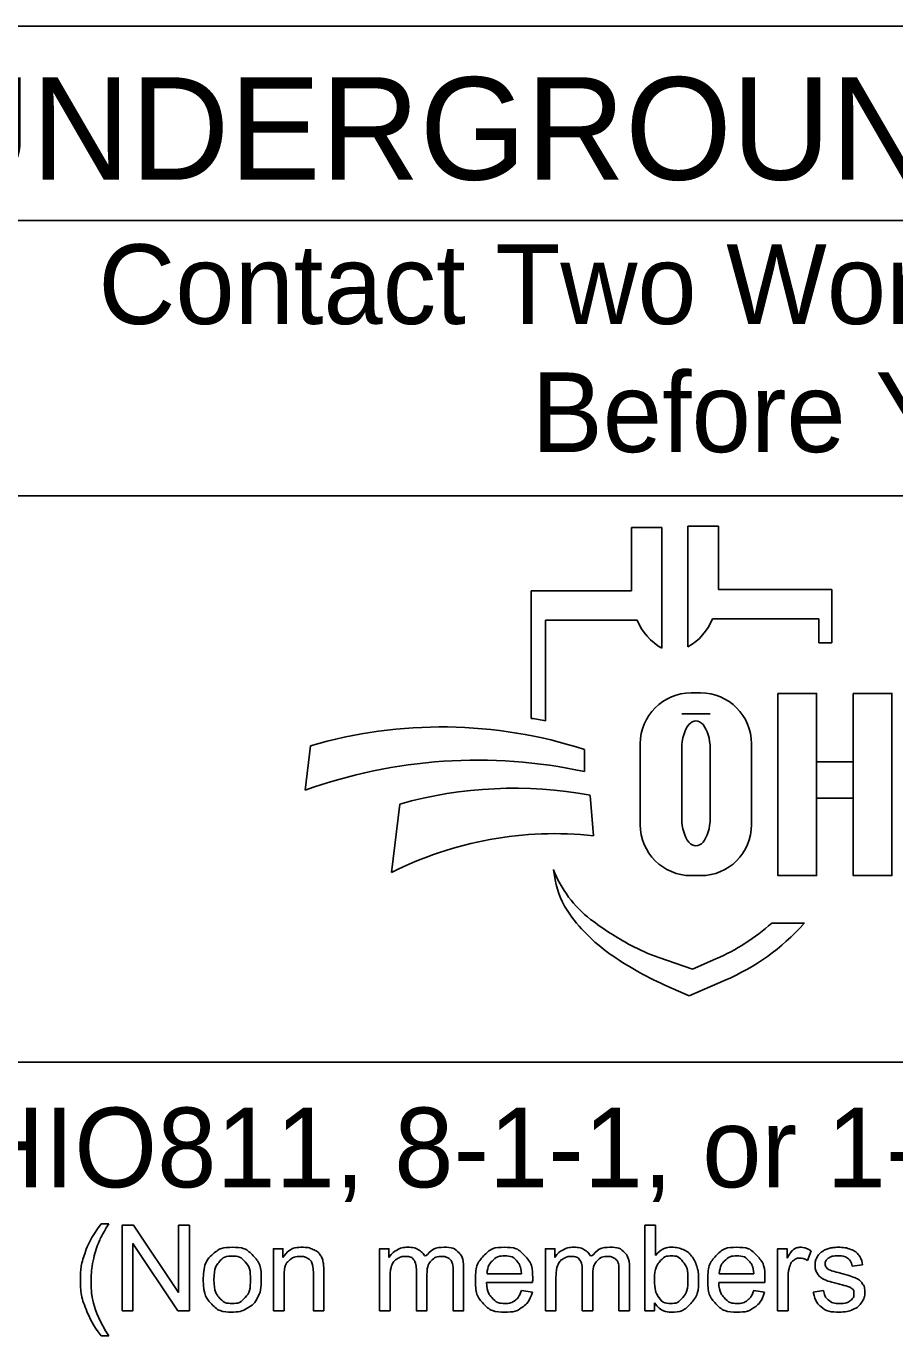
# Model space of a CAD drawing. Extents: x 0 to 34, y 0 to 22.
# Drawn here: x 2.67 to 4.196, y 2.18 to 4.48 of the extents above; entities that cross this region are included whole.
import ezdxf

# ---------------------------------------------------------------- set-up
doc = ezdxf.new("R2010")
doc.units = 0
doc.layers.add('SH_Data', color=7, linetype='Continuous')
doc.layers.add('SH_Text', color=7, linetype='Continuous')

msp = doc.modelspace()

# ---------------------------------------------------------------- linework, layer by layer
at = {"layer": 'SH_Data'}
for p, q in [((6.6275, 4.4803), (2.3775, 4.4803)), ((2.3775, 4.1387), (6.6275, 4.1387)), ((2.3775, 3.6553), (6.6275, 3.6553)), ((6.6275, 2.6607), (2.3775, 2.6607))]:
    msp.add_line(p, q, dxfattribs=at)
at = {"layer": 'SH_Text'}
for p, q in [((3.7335, 3.4883), (3.7335, 3.5998)), ((3.7335, 3.5998), (3.7872, 3.5998)), ((3.7872, 3.5998), (3.7872, 3.3877)), ((3.8329, 3.39), (3.8329, 3.6021)), ((3.8329, 3.6021), (3.8865, 3.6021)), ((3.8865, 3.6021), (3.8865, 3.4906)), ((3.5576, 3.2644), (3.5576, 3.4883)), ((3.5576, 3.4883), (3.7335, 3.4883)), ((3.8865, 3.4906), (4.0857, 3.4906)), ((4.0857, 3.4906), (4.0857, 3.3968)), ((3.5828, 3.4369), (3.5828, 3.26)), ((3.7439, 3.4369), (3.5828, 3.4369)), ((4.0625, 3.4392), (3.8761, 3.4392)), ((4.0625, 3.3968), (4.0625, 3.4392)), ((4.0857, 3.3968), (4.0625, 3.3968)), ((3.8385, 3.3091), (3.8551, 3.3091)), ((3.8718, 3.2721), (3.822, 3.2721)), ((3.1602, 3.1381), (3.1696, 3.2162)), ((3.6509, 3.2097), (3.6509, 3.1709)), ((3.7491, 3.0776), (3.7491, 3.2196)), ((3.822, 3.089), (3.822, 3.2114)), ((3.8718, 3.2114), (3.8718, 3.089)), ((3.9445, 3.2196), (3.9445, 3.0776)), ((3.6608, 3.1291), (3.6671, 3.0582)), ((3.312, 2.9936), (3.3267, 3.1137)), ((3.5997, 2.9807), (3.5967, 2.9986)), ((3.8551, 2.9882), (3.8385, 2.9882)), ((3.98, 2.9048), (4.0375, 2.9048)), ((3.7816, 2.8444), (3.841, 2.8239)), ((3.841, 2.8239), (3.8821, 2.8417)), ((3.835, 2.7769), (3.7976, 2.7934)), ((3.8983, 2.8044), (3.835, 2.7769))]:
    msp.add_line(p, q, dxfattribs=at)
for points in [[(3.991, 3.3081), (4.0589, 3.3081), (4.0589, 2.9881), (3.991, 2.9881)], [(4.1231, 3.3081), (4.1911, 3.3081), (4.1911, 2.9881), (4.1231, 2.9881)], [(4.0589, 3.1882), (4.1231, 3.1882), (4.1231, 3.1242), (4.0589, 3.1242)]]:
    msp.add_lwpolyline(points, close=True, dxfattribs=at)
for points in [[(2.8021, 2.3766), (2.8153, 2.3766)], [(2.8389, 2.2239), (2.8389, 2.3741), (2.8592, 2.3741), (2.9382, 2.2561), (2.9382, 2.3741), (2.9572, 2.3741), (2.9572, 2.2239), (2.9369, 2.2239), (2.8579, 2.3419), (2.8579, 2.2239), (2.8389, 2.2239)], [(3.7743, 2.2239), (3.7573, 2.2239), (3.7573, 2.3741), (3.7757, 2.3741), (3.7757, 2.3206)], [(3.1048, 2.2239), (3.1048, 2.3328), (3.1214, 2.3328), (3.1214, 2.3173)], [(3.2912, 2.2239), (3.2912, 2.3328), (3.3077, 2.3328), (3.3077, 2.3174)], [(3.5826, 2.2239), (3.5826, 2.3328), (3.5991, 2.3328), (3.5991, 2.3174)], [(3.9904, 2.2239), (3.9904, 2.3328), (4.007, 2.3328), (4.007, 2.3163)], [(4.0495, 2.3293), (4.043, 2.3122)], [(4.1394, 2.3046), (4.1213, 2.3022)], [(3.1233, 2.2833), (3.1233, 2.2239), (3.1048, 2.2239)], [(3.1932, 2.2908), (3.1932, 2.2239), (3.1748, 2.2239), (3.1748, 2.2901)], [(3.3097, 2.2803), (3.3097, 2.2239), (3.2912, 2.2239)], [(3.3743, 2.2871), (3.3743, 2.2239), (3.3559, 2.2239), (3.3559, 2.2946)], [(3.4388, 2.2986), (3.4388, 2.2239), (3.4203, 2.2239), (3.4203, 2.2924)], [(3.4799, 2.2887), (3.5406, 2.2887)], [(3.601, 2.2803), (3.601, 2.2239), (3.5826, 2.2239)], [(3.6657, 2.2871), (3.6657, 2.2239), (3.6473, 2.2239), (3.6473, 2.2946)], [(3.7301, 2.2986), (3.7301, 2.2239), (3.7117, 2.2239), (3.7117, 2.2924)], [(3.8879, 2.2887), (3.9486, 2.2887)], [(4.0088, 2.2809), (4.0088, 2.2239), (3.9904, 2.2239)], [(3.56, 2.2736), (3.4788, 2.2736)], [(3.5404, 2.2591), (3.5595, 2.2567)], [(3.968, 2.2736), (3.8868, 2.2736)], [(3.9484, 2.2591), (3.9675, 2.2567)], [(4.053, 2.2564), (4.0712, 2.2593)], [(3.7743, 2.2375), (3.7743, 2.2239)], [(2.8153, 2.1798), (2.8021, 2.1798)]]:
    msp.add_lwpolyline(points, dxfattribs=at)
for centre, radius, start, end in [((3.8353, 3.4736), 0.0985, 201.9296, 240.7469), ((3.7847, 3.476), 0.0985, 299.2531, 338.0704), ((3.8385, 3.2196), 0.0895, 90, 180), ((3.8551, 3.2196), 0.0895, 0, 90), ((3.3997, 2.4302), 0.8191, 72.1402, 106.3144), ((3.4295, 2.4554), 0.8191, 79.2074, 81.0007), ((3.4628, 2.2991), 0.8919, 77.8238, 109.8274), ((3.5267, 2.4094), 0.7322, 79.44, 105.8467), ((3.5987, 2.4262), 0.6357, 83.8248, 116.8021), ((3.8385, 3.0776), 0.0895, 180, 270), ((3.8551, 3.0776), 0.0895, 270, 0), ((3.7841, 3.0707), 0.2008, 201.0457, 232.5314), ((3.741, 3.0048), 0.1433, 189.6817, 216.0884), ((3.8747, 3.1022), 0.3088, 216.0884, 235.7167), ((3.9766, 3.3219), 0.5173, 232.5314, 241.794), ((3.7387, 3.1722), 0.3602, 293.4582, 312.0712), ((3.7387, 3.1722), 0.401, 293.4582, 317.8286), ((3.8914, 3.1631), 0.3371, 241.794, 250.9821), ((4.0412, 3.3465), 0.6044, 235.7167, 246.2325)]:
    msp.add_arc(centre, radius, start, end, dxfattribs=at)
for centre, start_param, end_param in [((3.8469, 3.2114), 4.712389, 7.853982), ((3.8469, 3.089), 1.570796, 4.712389)]:
    msp.add_ellipse(centre, major_axis=(0, 0.0484), ratio=0.514403, start_param=start_param, end_param=end_param, dxfattribs=at)
for points in [[(2.8021, 2.1798), (2.7869, 2.199), (2.7763, 2.2248), (2.7657, 2.2506), (2.7657, 2.2783), (2.7657, 2.3026), (2.7736, 2.325), (2.7829, 2.3509), (2.8021, 2.3766)], [(2.8153, 2.3766), (2.8029, 2.3553), (2.7989, 2.3462), (2.7927, 2.332), (2.7891, 2.3167), (2.7847, 2.2975), (2.7847, 2.2782), (2.7847, 2.2289), (2.8153, 2.1798)], [(2.9814, 2.2783), (2.9814, 2.3085), (2.9981, 2.3231), (3.0122, 2.3352), (3.0323, 2.3352), (3.0547, 2.3352), (3.069, 2.3205), (3.0832, 2.3058), (3.0832, 2.2799), (3.0832, 2.2589), (3.0769, 2.2469), (3.0706, 2.2348), (3.0586, 2.2282), (3.0466, 2.2215), (3.0323, 2.2215), (3.0095, 2.2215), (2.9954, 2.2362), (2.9814, 2.2508), (2.9814, 2.2783)], [(3.1214, 2.3173), (3.1334, 2.3352), (3.156, 2.3352), (3.1659, 2.3352), (3.1741, 2.3316), (3.1823, 2.3281), (3.1864, 2.3224), (3.1905, 2.3166), (3.1922, 2.3087), (3.1932, 2.3036), (3.1932, 2.2908)], [(3.3077, 2.3174), (3.3128, 2.3254), (3.3214, 2.3303), (3.3299, 2.3352), (3.3407, 2.3352), (3.3528, 2.3352), (3.3606, 2.3301), (3.3683, 2.3251), (3.3715, 2.3161), (3.3844, 2.3352), (3.4051, 2.3352), (3.4213, 2.3352), (3.43, 2.3262), (3.4388, 2.3172), (3.4388, 2.2986)], [(3.5595, 2.2567), (3.555, 2.24), (3.5428, 2.2307), (3.5306, 2.2215), (3.5117, 2.2215), (3.4878, 2.2215), (3.4738, 2.2362), (3.4598, 2.2509), (3.4598, 2.2774), (3.4598, 2.3049), (3.474, 2.32), (3.4881, 2.3352), (3.5106, 2.3352), (3.5324, 2.3352), (3.5463, 2.3203), (3.5601, 2.3055), (3.5601, 2.2785), (3.5601, 2.2769), (3.56, 2.2736)], [(3.5991, 2.3174), (3.6042, 2.3254), (3.6127, 2.3303), (3.6212, 2.3352), (3.6321, 2.3352), (3.6442, 2.3352), (3.6519, 2.3301), (3.6597, 2.3251), (3.6628, 2.3161), (3.6758, 2.3352), (3.6965, 2.3352), (3.7127, 2.3352), (3.7214, 2.3262), (3.7301, 2.3172), (3.7301, 2.2986)], [(3.7757, 2.3206), (3.7874, 2.3352), (3.8055, 2.3352), (3.8155, 2.3352), (3.8245, 2.3311), (3.8335, 2.3271), (3.8392, 2.3198), (3.845, 2.3124), (3.8483, 2.3021), (3.8516, 2.2918), (3.8516, 2.28), (3.8516, 2.252), (3.8378, 2.2368), (3.8239, 2.2215), (3.8046, 2.2215), (3.7853, 2.2215), (3.7743, 2.2375)], [(3.9675, 2.2567), (3.963, 2.24), (3.9508, 2.2307), (3.9386, 2.2215), (3.9196, 2.2215), (3.8958, 2.2215), (3.8818, 2.2362), (3.8678, 2.2509), (3.8678, 2.2774), (3.8678, 2.3049), (3.882, 2.32), (3.8961, 2.3352), (3.9186, 2.3352), (3.9404, 2.3352), (3.9543, 2.3203), (3.9681, 2.3055), (3.9681, 2.2785), (3.9681, 2.2769), (3.968, 2.2736)], [(4.007, 2.3163), (4.0133, 2.3278), (4.0187, 2.3315), (4.0241, 2.3352), (4.0305, 2.3352), (4.0398, 2.3352), (4.0495, 2.3293)], [(4.0712, 2.2593), (4.0727, 2.2483), (4.0798, 2.2425), (4.0868, 2.2366), (4.0995, 2.2366), (4.1122, 2.2366), (4.1184, 2.2418), (4.1245, 2.247), (4.1245, 2.254), (4.1245, 2.2602), (4.1191, 2.2638), (4.1153, 2.2663), (4.1002, 2.2701), (4.0799, 2.2752), (4.072, 2.2789), (4.0642, 2.2827), (4.0601, 2.2893), (4.0561, 2.2959), (4.0561, 2.3038), (4.0561, 2.3111), (4.0594, 2.3173), (4.0628, 2.3235), (4.0685, 2.3276), (4.0728, 2.3308), (4.0803, 2.333), (4.0877, 2.3352), (4.0962, 2.3352), (4.109, 2.3352), (4.1187, 2.3315), (4.1284, 2.3278), (4.133, 2.3215), (4.1377, 2.3152), (4.1394, 2.3046)], [(3.0003, 2.2783), (3.0003, 2.2574), (3.0094, 2.247), (3.0185, 2.2366), (3.0323, 2.2366), (3.046, 2.2366), (3.0551, 2.2471), (3.0642, 2.2575), (3.0642, 2.279), (3.0642, 2.2991), (3.0551, 2.3095), (3.0459, 2.3199), (3.0323, 2.3199), (3.0185, 2.3199), (3.0094, 2.3096), (3.0003, 2.2992), (3.0003, 2.2783)], [(3.1748, 2.2901), (3.1748, 2.3013), (3.1726, 2.3069), (3.1705, 2.3125), (3.165, 2.3158), (3.1595, 2.3191), (3.1521, 2.3191), (3.1404, 2.3191), (3.1318, 2.3117), (3.1233, 2.3042), (3.1233, 2.2833)], [(3.3559, 2.2946), (3.3559, 2.3069), (3.3514, 2.313), (3.3469, 2.3191), (3.3366, 2.3191), (3.3288, 2.3191), (3.3222, 2.315), (3.3156, 2.311), (3.3126, 2.3031), (3.3097, 2.2952), (3.3097, 2.2803)], [(3.4203, 2.2924), (3.4203, 2.3035), (3.4185, 2.3083), (3.4168, 2.3132), (3.412, 2.3162), (3.4073, 2.3191), (3.401, 2.3191), (3.3895, 2.3191), (3.3819, 2.3115), (3.3743, 2.3039), (3.3743, 2.2871)], [(3.5406, 2.2887), (3.5394, 2.3025), (3.5337, 2.3094), (3.5249, 2.3201), (3.5108, 2.3201), (3.4981, 2.3201), (3.4894, 2.3115), (3.4808, 2.303), (3.4799, 2.2887)], [(3.6473, 2.2946), (3.6473, 2.3069), (3.6428, 2.313), (3.6383, 2.3191), (3.628, 2.3191), (3.6202, 2.3191), (3.6136, 2.315), (3.607, 2.311), (3.604, 2.3031), (3.601, 2.2952), (3.601, 2.2803)], [(3.7117, 2.2924), (3.7117, 2.3035), (3.7099, 2.3083), (3.7081, 2.3132), (3.7034, 2.3162), (3.6987, 2.3191), (3.6923, 2.3191), (3.6809, 2.3191), (3.6733, 2.3115), (3.6657, 2.3039), (3.6657, 2.2871)], [(3.7741, 2.2792), (3.7741, 2.2596), (3.7794, 2.2509), (3.7881, 2.2366), (3.8029, 2.2366), (3.815, 2.2366), (3.8238, 2.2471), (3.8326, 2.2576), (3.8326, 2.2784), (3.8326, 2.2998), (3.8241, 2.3099), (3.8157, 2.3201), (3.8038, 2.3201), (3.7917, 2.3201), (3.7829, 2.3096), (3.7741, 2.299), (3.7741, 2.2792)], [(3.9486, 2.2887), (3.9474, 2.3025), (3.9417, 2.3094), (3.9328, 2.3201), (3.9188, 2.3201), (3.9061, 2.3201), (3.8974, 2.3115), (3.8888, 2.303), (3.8879, 2.2887)], [(4.043, 2.3122), (4.0363, 2.3162), (4.0295, 2.3162), (4.0235, 2.3162), (4.0187, 2.3125), (4.0139, 2.3089), (4.0119, 2.3024), (4.0088, 2.2926), (4.0088, 2.2809)], [(4.1213, 2.3022), (4.1201, 2.3106), (4.1142, 2.3153), (4.1083, 2.3201), (4.0975, 2.3201), (4.0848, 2.3201), (4.0794, 2.3159), (4.0739, 2.3116), (4.0739, 2.306), (4.0739, 2.3024), (4.0762, 2.2995), (4.0785, 2.2966), (4.0833, 2.2946), (4.086, 2.2936), (4.0996, 2.2899), (4.1192, 2.2847), (4.1269, 2.2813), (4.1347, 2.278), (4.1391, 2.2717), (4.1435, 2.2653), (4.1435, 2.2559), (4.1435, 2.2467), (4.1381, 2.2386), (4.1327, 2.2304), (4.1226, 2.226), (4.1124, 2.2215), (4.0996, 2.2215), (4.0784, 2.2215), (4.0672, 2.2303), (4.0561, 2.2391), (4.053, 2.2564)], [(3.4788, 2.2736), (3.4799, 2.2557), (3.489, 2.2462), (3.4981, 2.2366), (3.5117, 2.2366), (3.5219, 2.2366), (3.5291, 2.242), (3.5362, 2.2473), (3.5404, 2.2591)], [(3.8868, 2.2736), (3.8879, 2.2557), (3.897, 2.2462), (3.9061, 2.2366), (3.9197, 2.2366), (3.9299, 2.2366), (3.937, 2.242), (3.9442, 2.2473), (3.9484, 2.2591)]]:
    msp.add_open_spline(points, degree=3, dxfattribs=at)

# ---------------------------------------------------------------- texts
for s, height, p in [('UNDERGROUND UTILITIES', 0.18, (2.5057, 4.2106)), ('Contact Two Working Days', 0.14, (2.7972, 3.9571)), ('Before You Dig', 0.14, (3.5583, 3.7321)), ('OHIO811, 8-1-1, or 1-800-362-2764', 0.14, (2.422, 2.4406))]:
    msp.add_text(s, height=height, dxfattribs=at).set_placement(p)

doc.saveas('drawing.dxf')
